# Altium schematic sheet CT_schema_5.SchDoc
size 252 x 159 mm
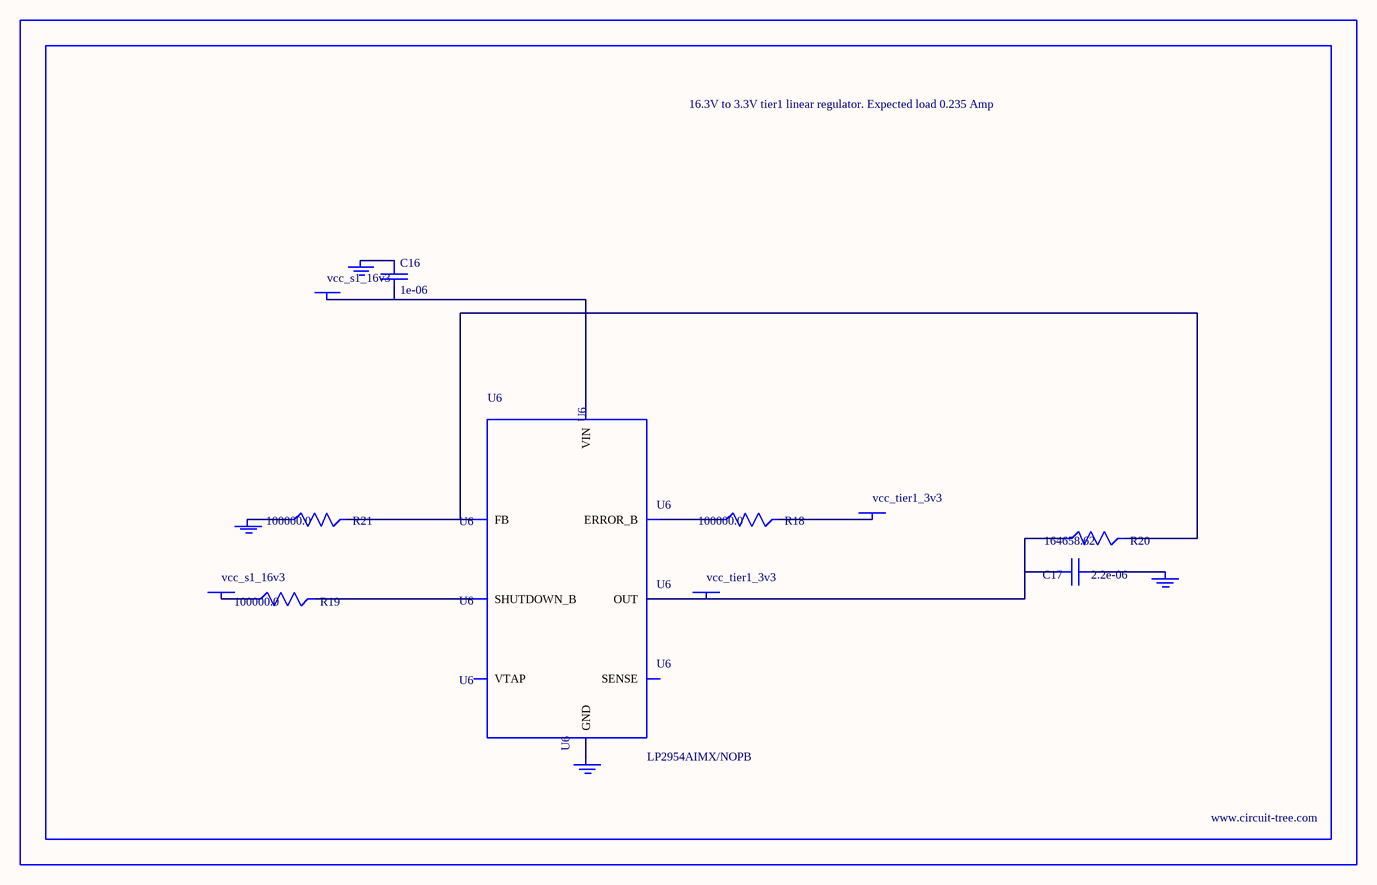
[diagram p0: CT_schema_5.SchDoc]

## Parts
BORDER4  (no value)
C16  1e-06  [EXV-9B]
C17  2.2e-06  [EXV-9B]
GND_INSTANCE_4_0  (no value)
GND_INSTANCE_4_1  (no value)
GND_INSTANCE_4_2  (no value)
GND_INSTANCE_4_3  (no value)
POWER_INSTANCE_4_0  vcc_s1_16v3
POWER_INSTANCE_4_1  vcc_tier1_3v3
POWER_INSTANCE_4_2  vcc_s1_16v3
POWER_INSTANCE_4_3  vcc_tier1_3v3
R18  100000.0  [R0603]
R19  100000.0  [R0603]
R20  164658.62  [R0603]
R21  100000.0  [R0603]
U6  LP2954AIMX/NOPB  [LP2954]

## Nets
NetC16_1: C16.1 GND_INSTANCE_4_2.0(GND)
NetC16_2: C16.2 POWER_INSTANCE_4_2.0(PWR) U6.8(VIN)
NetC17_1: C17.1 GND_INSTANCE_4_0.0(GND)
NetC17_2: C17.2 POWER_INSTANCE_4_3.0(PWR) R20.1 U6.1(OUT)
NetGND_INSTANCE_4_1_0: GND_INSTANCE_4_1.0(GND) R21.1
NetGND_INSTANCE_4_3_0: GND_INSTANCE_4_3.0(GND) U6.4(GND)
NetPOWER_INSTANCE_4_0_0: POWER_INSTANCE_4_0.0(PWR) R19.1
NetPOWER_INSTANCE_4_1_0: POWER_INSTANCE_4_1.0(PWR) R18.2
NetR18_1: R18.1 U6.5(ERROR_B)
NetR19_2: R19.2 U6.3(SHUTDOWN_B)
NetR20_2: R20.2 R21.2 U6.7(FB)

Not connected (* = marked no-connect by the designer): U6 2(SENSE) 6(VTAP)

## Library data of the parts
BORDER4 = BORDER_PAGE4
C16 = EDK105M050A9BAA
C17 = EDK225M050A9BAA
GND_INSTANCE_4_0-GND_INSTANCE_4_3 = GND
POWER_INSTANCE_4_0-POWER_INSTANCE_4_3 = PWR
R18 R19 R21 = RC0603JR-07100KL
R20 = R20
